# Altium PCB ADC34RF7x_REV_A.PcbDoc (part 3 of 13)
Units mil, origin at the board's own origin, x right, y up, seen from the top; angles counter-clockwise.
Board outline 6250 x 2716.54 mil, 18 copper layers (Top Layer, L2 GND, L3 PWR, L4 GND, L5 PWR/SIG, L6 GND, L7 SIGNAL, L8 GND, L9 GND, L10 SIGNAL, L11 GND, L12 SIGNAL, L13 GND, L14 PWR, L15 GND, L16 PWR/SIG, L16 GND, Bottom Layer), stack 95.314 mil thick; 668 components, 786 nets, 3150 pads, 2020 vias.
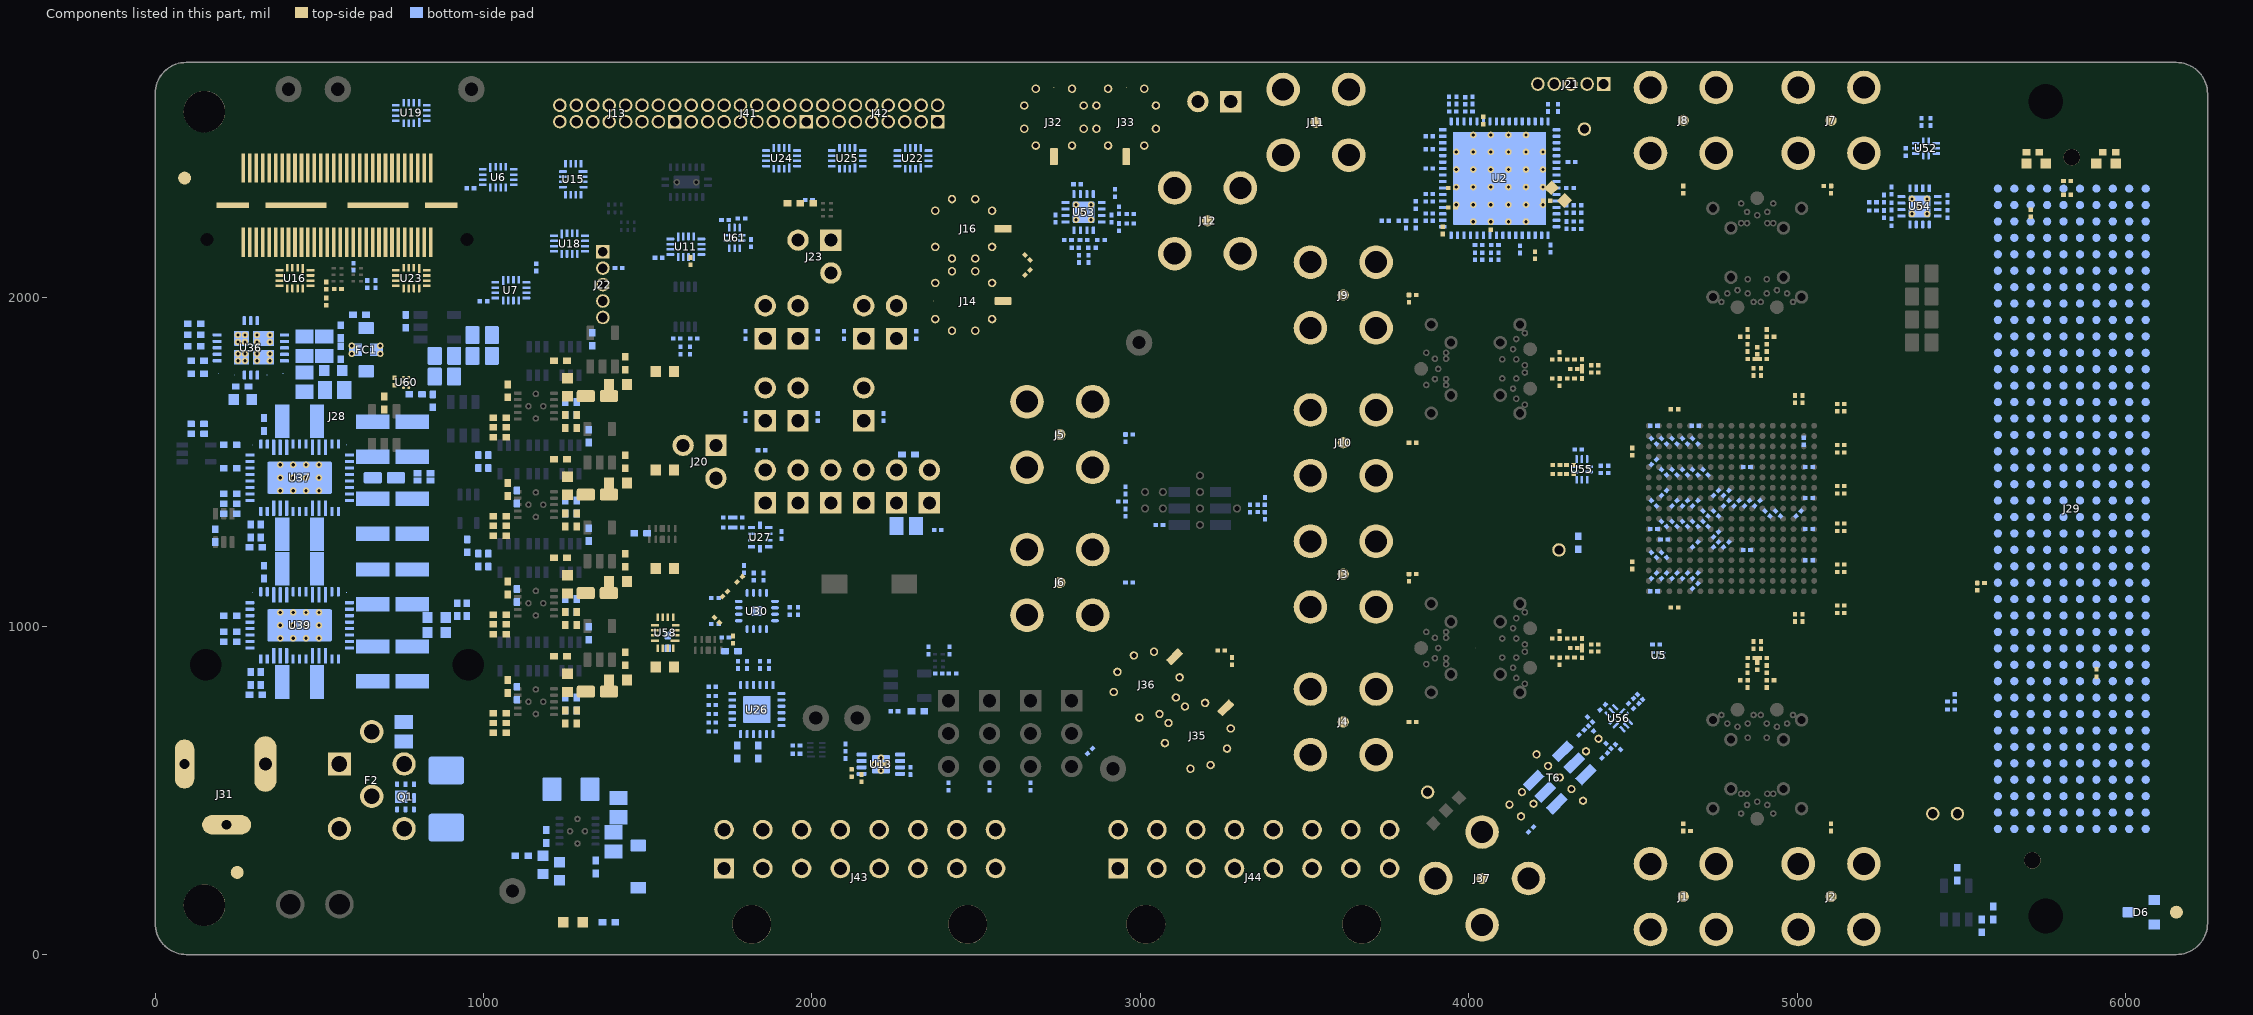
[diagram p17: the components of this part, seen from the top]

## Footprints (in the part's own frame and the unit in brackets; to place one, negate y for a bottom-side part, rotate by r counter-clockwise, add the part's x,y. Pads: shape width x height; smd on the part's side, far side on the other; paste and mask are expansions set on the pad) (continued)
NKD0064A [mm] "QFN, 64-Leads, Body 9x9mm, Pitch 0.5mm"
  rrect40% 0.6x0.25 smd mask+0.07: 1(-4.4,3.75) 2(-4.4,3.25) 3(-4.4,2.75) 4(-4.4,2.25) 5(-4.4,1.75) 6(-4.4,1.25) 7(-4.4,0.75) 8(-4.4,0.25) 9(-4.4,-0.25) 10(-4.4,-0.75) 11(-4.4,-1.25) 12(-4.4,-1.75) 13(-4.4,-2.25) 14(-4.4,-2.75) 15(-4.4,-3.25) 16(-4.4,-3.75) 33(4.4,-3.75) 34(4.4,-3.25) 35(4.4,-2.75) 36(4.4,-2.25) 37(4.4,-1.75) 38(4.4,-1.25) 39(4.4,-0.75) 40(4.4,-0.25) 41(4.4,0.25) 42(4.4,0.75) 43(4.4,1.25) 44(4.4,1.75) 45(4.4,2.25) 46(4.4,2.75) 47(4.4,3.25) 48(4.4,3.75)
  rrect40% 0.25x0.6 smd mask+0.07: 17(-3.75,-4.4) 18(-3.25,-4.4) 19(-2.75,-4.4) 20(-2.25,-4.4) 21(-1.75,-4.4) 22(-1.25,-4.4) 23(-0.75,-4.4) 24(-0.25,-4.4) 25(0.25,-4.4) 26(0.75,-4.4) 27(1.25,-4.4) 28(1.75,-4.4) 29(2.25,-4.4) 30(2.75,-4.4) 31(3.25,-4.4) 32(3.75,-4.4) 49(3.75,4.4) 50(3.25,4.4) 51(2.75,4.4) 52(2.25,4.4) 53(1.75,4.4) 54(1.25,4.4) 55(0.75,4.4) 56(0.25,4.4) 57(-0.25,4.4) 58(-0.75,4.4) 59(-1.25,4.4) 60(-1.75,4.4) 61(-2.25,4.4) 62(-2.75,4.4) 63(-3.25,4.4) 64(-3.75,4.4)
  round 0.508 hole 0.254 mask+0.102: 65(-3.35,-2.04) 65(-3.35,-0.68) 65(-3.35,0.68) 65(-3.35,2.04) 65(-2.04,-3.35) 65(-2.04,-2.04) 65(-2.04,-0.68) 65(-2.04,0.68) 65(-2.04,2.04) 65(-2.04,3.35) 65(-0.68,-3.35) 65(-0.68,-2.04) 65(-0.68,-0.68) 65(-0.68,0.68) 65(-0.68,2.04) 65(-0.68,3.35) 65(0.68,-3.35) 65(0.68,-2.04) 65(0.68,-0.68) 65(0.68,0.68) 65(0.68,2.04) 65(0.68,3.35) 65(2.04,-3.35) 65(2.04,-2.04) 65(2.04,-0.68) 65(2.04,0.68) 65(2.04,2.04) 65(2.04,3.35) 65(3.35,-2.04) 65(3.35,-0.68) 65(3.35,0.68) 65(3.35,2.04)
  rrect1% 7.2x7.2 smd paste-3.6 mask+0.07: 65(0,0)
  silkscreen extent -4.65,-4.65 4.65,4.65, body extent -4.55,-4.55 4.55,4.55, height 0.8
NKG0010A [mm]
  rrect50% 0.6x0.2 smd paste+0 mask+0.05: 1(-0.55,0.2) 2(-0.55,-0.2) 6(0.55,-0.2) 7(0.55,0.2)
  rrect50% 0.2x0.6 smd paste+0 mask+0.05: 3(-0.4,-0.8) 4(0,-0.8) 5(0.4,-0.8) 8(0.4,0.8) 9(0,0.8) 10(-0.4,0.8)
  silkscreen extent -1.07,0.47 -0.93,0.62, body extent -0.72,-0.93 0.72,0.93, height 0.56
PBC02SAAN [mm] "Sullins 100mil, 1x2, 230 mil above insulator"
  rect 1.65x1.65 hole 1.016: 1(0,1.27)
  round 1.65 hole 1.016: 2(0,-1.27)
  silkscreen extent -1.27,-2.54 1.6,2.54, body extent -1.27,-2.54 1.27,2.54, height 8.38
ProbePoint_TH_40mil [mil]
  round 41 hole 28: 1(0,0)
RAPC722X [mm] "Conn_DC Jack"
  oval 1.7x4.3 hole 1.01 slot 3.56 at 90 deg: 1(14.194,0)
  oval 1.5x3.8 hole 0.76 slot 3.05 at 90 deg: 2(7.946,0)
  oval 3.8x1.5 hole 0.76 slot 3.05 at 0 deg: 3(11.197,-4.7)
  silkscreen extent 0.2,-4.57 14.93,4.57, body extent 0.58,-4.97 15.06,4.56, height 10.92
RDB0051A [mm]
  round 0.025 smd mask+0.05: 1(-2.54,3.625) 15(-2.54,-3.625) 24(2.54,-3.625) 38(2.54,3.625)
  rrect30% 0.7x0.25 smd paste+0 mask+0.05: 2(-2.6,3) 3(-2.6,2.5) 7(-2.6,0.5) 8(-2.6,0) 9(-2.6,-0.5) 13(-2.6,-2.5) 14(-2.6,-3) 25(2.6,-3) 26(2.6,-2.5) 30(2.6,-0.5) 31(2.6,0) 32(2.6,0.5) 36(2.6,2.5) 37(2.6,3)
  rrect30% 1.2x0.25 smd paste+0 mask+0.05: 4(-2.35,2) 5(-2.35,1.5) 6(-2.35,1) 10(-2.35,-1) 11(-2.35,-1.5) 12(-2.35,-2) 27(2.35,-2) 28(2.35,-1.5) 29(2.35,-1) 33(2.35,1) 34(2.35,1.5) 35(2.35,2)
  rrect30% 0.25x0.7 smd paste+0 mask+0.05: 16(-1.75,-3.85) 17(-1.25,-3.85) 18(-0.75,-3.85) 19(-0.25,-3.85) 20(0.25,-3.85) 21(0.75,-3.85) 22(1.25,-3.85) 23(1.75,-3.85) 39(1.75,3.85) 40(1.25,3.85) 41(0.75,3.85) 42(0.25,3.85) 43(-0.25,3.85) 44(-0.75,3.85) 45(-1.25,3.85) 46(-1.75,3.85)
  rrect10% 2.5x5 smd paste-5: 47(0,0)
  round 0.508 hole 0.254 mask+0.102: 48(-1,1.5) 48(0,1.5) 48(1,1.5) 49(-1,0.5) 49(0,0.5) 49(1,0.5) 50(-1,-0.5) 50(0,-0.5) 50(1,-0.5) 51(-1,-1.5) 51(0,-1.5) 51(1,-1.5)
  Top Layer region: 2.955,-3.624 2.955,-3.425 2.951,-3.406 2.94,-3.389 2.924,-3.378 2.904,-3.375 2.904,-3.375 2.175,-3.375 2.156,-3.379 2.139,-3.39 2.129,-3.406 2.125,-3.426 2.125,-3.426 2.125,-3.825 2.129,-3.844 2.14,-3.861 2.157,-3.871 2.176,-3.875 2.176,-3.875 2.375,-3.875 2.394,-3.871 2.411,-3.86 2.422,-3.843 2.425,-3.824 2.425,-3.824 2.425,-3.726 2.429,-3.706 2.439,-3.69 2.456,-3.679 2.475,-3.675 2.475,-3.675 2.9,-3.675 2.921,-3.673 2.939,-3.662 2.951,-3.645 2.955,-3.624
  Top Layer region: -2.955,-3.624 -2.955,-3.425 -2.951,-3.406 -2.94,-3.389 -2.923,-3.378 -2.904,-3.375 -2.904,-3.375 -2.175,-3.375 -2.156,-3.379 -2.139,-3.39 -2.128,-3.406 -2.125,-3.426 -2.125,-3.426 -2.125,-3.825 -2.129,-3.844 -2.14,-3.861 -2.156,-3.871 -2.176,-3.875 -2.176,-3.875 -2.375,-3.875 -2.394,-3.871 -2.411,-3.86 -2.421,-3.843 -2.425,-3.824 -2.425,-3.824 -2.425,-3.726 -2.428,-3.706 -2.439,-3.69 -2.456,-3.679 -2.475,-3.675 -2.475,-3.675 -2.9,-3.675 -2.921,-3.673 -2.939,-3.662 -2.951,-3.645 -2.955,-3.624
  Top Layer region: 2.955,3.624 2.955,3.425 2.951,3.406 2.94,3.389 2.924,3.379 2.904,3.375 2.904,3.375 2.175,3.375 2.156,3.379 2.139,3.39 2.129,3.407 2.125,3.426 2.125,3.426 2.125,3.825 2.129,3.844 2.14,3.861 2.157,3.872 2.176,3.875 2.176,3.875 2.375,3.875 2.394,3.871 2.411,3.86 2.422,3.844 2.425,3.824 2.425,3.824 2.425,3.726 2.429,3.707 2.439,3.69 2.456,3.679 2.475,3.675 2.475,3.675 2.9,3.675 2.921,3.673 2.939,3.662 2.951,3.645 2.955,3.624
  Top Layer region: -2.955,3.624 -2.955,3.425 -2.951,3.406 -2.94,3.389 -2.923,3.379 -2.904,3.375 -2.904,3.375 -2.175,3.375 -2.156,3.379 -2.139,3.39 -2.128,3.407 -2.125,3.426 -2.125,3.426 -2.125,3.825 -2.129,3.844 -2.14,3.861 -2.156,3.872 -2.176,3.875 -2.176,3.875 -2.375,3.875 -2.394,3.871 -2.411,3.86 -2.421,3.844 -2.425,3.824 -2.425,3.824 -2.425,3.726 -2.428,3.707 -2.439,3.69 -2.456,3.679 -2.475,3.675 -2.475,3.675 -2.9,3.675 -2.921,3.673 -2.939,3.662 -2.951,3.645 -2.955,3.624
  silkscreen extent -3.65,-4.3 2.8,4.3, body extent -2.75,-4 2.75,4, height 1.8
RDU0028A [mm]
  round 0.025 smd mask+0.05: 1(-1.987,2.487) 2(-2.1,1.25) 6(-2.1,-1.25) 7(-1.987,-2.488) 13(1.987,-2.488) 14(2.1,-1.25) 18(2.1,1.25) 19(1.988,2.488)
  rrect40% 0.7x0.25 smd paste+0 mask+0.05: 3(-2.1,0.5) 4(-2.1,0) 5(-2.1,-0.5) 15(2.1,-0.5) 16(2.1,0) 17(2.1,0.5)
  rrect40% 0.25x0.7 smd paste+0 mask+0.05: 8(-1,-2.6) 9(-0.5,-2.6) 10(0,-2.6) 11(0.5,-2.6) 12(1,-2.6) 20(1,2.6) 21(0.5,2.6) 22(0,2.6) 23(-0.5,2.6) 24(-1,2.6)
  round 0.508 hole 0.254 mask+0.102: 25(-1,1) 25(-1,0.45) 25(-0.45,1) 25(-0.45,0.45) 26(-1,-1.475) 26(-1,-0.475) 26(-0.45,-1.475) 26(-0.45,-0.475) 27(0.45,-1.475) 27(0.45,-0.475) 27(1,-1.475) 27(1,-0.475) 28(0.45,1) 28(0.45,0.45) 28(1,1) 28(1,0.45)
  rrect9% 1.15x1.15 smd paste-1000 mask+0.05: 25(-0.725,0.725) 28(0.725,0.725)
  rrect9% 1.15x1.65 smd paste-1000 mask+0.05: 26(-0.725,-0.975) 27(0.725,-0.975)
  Top Layer region: -2.4,1.625 -1.8,1.625 -1.781,1.621 -1.765,1.61 -1.754,1.594 -1.75,1.575 -1.75,1.575 -1.75,0.925 -1.754,0.906 -1.765,0.89 -1.781,0.879 -1.8,0.875 -1.8,0.875 -2.4,0.875 -2.419,0.879 -2.435,0.89 -2.446,0.906 -2.45,0.925 -2.45,0.925 -2.45,1.075 -2.443,1.1 -2.425,1.118 -2.4,1.125 -2.4,1.125 -2.225,1.125 -2.187,1.133 -2.154,1.154 -2.133,1.187 -2.125,1.225 -2.125,1.225 -2.125,1.275 -2.138,1.325 -2.175,1.362 -2.225,1.375 -2.225,1.375 -2.4,1.375 -2.419,1.379 -2.435,1.39 -2.446,1.406 -2.45,1.425 -2.45,1.425 -2.45,1.575 -2.443,1.6 -2.425,1.618 -2.4,1.625
  Top Layer region: -1.575,-2.95 -1.55,-2.943 -1.532,-2.925 -1.525,-2.9 -1.525,-2.9 -1.525,-2.075 -1.529,-2.056 -1.54,-2.04 -1.556,-2.029 -1.575,-2.025 -1.575,-2.025 -2.4,-2.025 -2.423,-2.033 -2.439,-2.051 -2.445,-2.075 -2.445,-2.075 -2.45,-2.225 -2.443,-2.25 -2.425,-2.268 -2.4,-2.275 -2.4,-2.275 -2.225,-2.275 -2.187,-2.283 -2.154,-2.304 -2.133,-2.337 -2.125,-2.375 -2.125,-2.375 -2.125,-2.575 -2.118,-2.6 -2.1,-2.618 -2.075,-2.625 -2.075,-2.625 -1.875,-2.625 -1.837,-2.633 -1.804,-2.654 -1.783,-2.687 -1.775,-2.725 -1.775,-2.725 -1.775,-2.9 -1.768,-2.925 -1.75,-2.943 -1.725,-2.95 -1.725,-2.95
  Top Layer region: -1.575,2.95 -1.55,2.943 -1.532,2.925 -1.525,2.9 -1.525,2.9 -1.525,2.075 -1.529,2.056 -1.54,2.04 -1.556,2.029 -1.575,2.025 -1.575,2.025 -2.4,2.025 -2.423,2.033 -2.439,2.051 -2.445,2.075 -2.445,2.075 -2.45,2.225 -2.443,2.25 -2.425,2.268 -2.4,2.275 -2.4,2.275 -2.225,2.275 -2.187,2.283 -2.154,2.304 -2.133,2.337 -2.125,2.375 -2.125,2.375 -2.125,2.575 -2.118,2.6 -2.1,2.618 -2.075,2.625 -2.075,2.625 -1.875,2.625 -1.837,2.633 -1.804,2.654 -1.783,2.687 -1.775,2.725 -1.775,2.725 -1.775,2.9 -1.768,2.925 -1.75,2.943 -1.725,2.95 -1.725,2.95
  Top Layer region: -2.4,-0.875 -1.8,-0.875 -1.775,-0.882 -1.757,-0.9 -1.75,-0.925 -1.75,-0.925 -1.75,-1.575 -1.754,-1.594 -1.765,-1.61 -1.781,-1.621 -1.8,-1.625 -1.8,-1.625 -2.4,-1.625 -2.419,-1.621 -2.435,-1.61 -2.446,-1.594 -2.45,-1.575 -2.45,-1.575 -2.45,-1.425 -2.443,-1.4 -2.425,-1.382 -2.4,-1.375 -2.4,-1.375 -2.225,-1.375 -2.187,-1.367 -2.154,-1.346 -2.133,-1.313 -2.125,-1.275 -2.125,-1.275 -2.125,-1.225 -2.138,-1.175 -2.175,-1.138 -2.225,-1.125 -2.225,-1.125 -2.4,-1.125 -2.419,-1.121 -2.435,-1.11 -2.446,-1.094 -2.45,-1.075 -2.45,-1.075 -2.45,-0.925 -2.443,-0.9 -2.425,-0.882 -2.4,-0.875
  Top Layer region: 2.4,0.875 1.8,0.875 1.775,0.882 1.757,0.9 1.75,0.925 1.75,0.925 1.75,1.575 1.754,1.594 1.765,1.61 1.781,1.621 1.8,1.625 1.8,1.625 2.4,1.625 2.419,1.621 2.435,1.61 2.446,1.594 2.45,1.575 2.45,1.575 2.45,1.425 2.443,1.4 2.425,1.382 2.4,1.375 2.4,1.375 2.225,1.375 2.187,1.367 2.154,1.346 2.133,1.313 2.125,1.275 2.125,1.275 2.125,1.225 2.138,1.175 2.175,1.138 2.225,1.125 2.225,1.125 2.4,1.125 2.419,1.121 2.435,1.11 2.446,1.094 2.45,1.075 2.45,1.075 2.45,0.925 2.443,0.9 2.425,0.882 2.4,0.875
  Top Layer region: 1.575,-2.95 1.55,-2.943 1.532,-2.925 1.525,-2.9 1.525,-2.9 1.525,-2.075 1.529,-2.056 1.54,-2.04 1.556,-2.029 1.575,-2.025 1.575,-2.025 2.4,-2.025 2.423,-2.033 2.439,-2.051 2.445,-2.075 2.445,-2.075 2.45,-2.225 2.443,-2.25 2.425,-2.268 2.4,-2.275 2.4,-2.275 2.225,-2.275 2.187,-2.283 2.154,-2.304 2.133,-2.337 2.125,-2.375 2.125,-2.375 2.125,-2.575 2.118,-2.6 2.1,-2.618 2.075,-2.625 2.075,-2.625 1.875,-2.625 1.837,-2.633 1.804,-2.654 1.783,-2.687 1.775,-2.725 1.775,-2.725 1.775,-2.9 1.768,-2.925 1.75,-2.943 1.725,-2.95 1.725,-2.95
  Top Layer region: 2.4,-1.625 1.8,-1.625 1.775,-1.618 1.757,-1.6 1.75,-1.575 1.75,-1.575 1.75,-0.925 1.754,-0.906 1.765,-0.89 1.781,-0.879 1.8,-0.875 1.8,-0.875 2.4,-0.875 2.419,-0.879 2.435,-0.89 2.446,-0.906 2.45,-0.925 2.45,-0.925 2.45,-1.075 2.443,-1.1 2.425,-1.118 2.4,-1.125 2.4,-1.125 2.225,-1.125 2.187,-1.133 2.154,-1.154 2.133,-1.187 2.125,-1.225 2.125,-1.225 2.125,-1.275 2.138,-1.325 2.175,-1.362 2.225,-1.375 2.225,-1.375 2.4,-1.375 2.419,-1.379 2.435,-1.39 2.446,-1.406 2.45,-1.425 2.45,-1.425 2.45,-1.575 2.443,-1.6 2.425,-1.618 2.4,-1.625
  Top Layer region: 1.575,2.95 1.55,2.943 1.532,2.925 1.525,2.9 1.525,2.9 1.525,2.075 1.529,2.056 1.54,2.04 1.556,2.029 1.575,2.025 1.575,2.025 2.4,2.025 2.423,2.033 2.439,2.051 2.445,2.075 2.445,2.075 2.45,2.225 2.443,2.25 2.425,2.268 2.4,2.275 2.4,2.275 2.225,2.275 2.187,2.283 2.154,2.304 2.133,2.337 2.125,2.375 2.125,2.375 2.125,2.575 2.118,2.6 2.1,2.618 2.075,2.625 2.075,2.625 1.875,2.625 1.837,2.633 1.804,2.654 1.783,2.687 1.775,2.725 1.775,2.725 1.775,2.9 1.768,2.925 1.75,2.943 1.725,2.95 1.725,2.95
  silkscreen extent -3.2,-3.13 2.63,3.13, body extent -2.25,-2.75 2.25,2.75, height 1.9
RGE0024C [mm] "VQFN-24"
  rrect42% 0.6x0.24 smd: 1(-1.9,1.25) 2(-1.9,0.75) 3(-1.9,0.25) 4(-1.9,-0.25) 5(-1.9,-0.75) 6(-1.9,-1.25) 13(1.9,-1.25) 14(1.9,-0.75) 15(1.9,-0.25) 16(1.9,0.25) 17(1.9,0.75) 18(1.9,1.25)
  rrect42% 0.24x0.6 smd: 7(-1.25,-1.9) 8(-0.75,-1.9) 9(-0.25,-1.9) 10(0.25,-1.9) 11(0.75,-1.9) 12(1.25,-1.9) 19(1.25,1.9) 20(0.75,1.9) 21(0.25,1.9) 22(-0.25,1.9) 23(-0.75,1.9) 24(-1.25,1.9)
  rrect5% 2.1x2.1 smd paste-1.05: 25(0,0)
  body extent -2,-2 2,2, height 1
RGT0016C [mm]
  rrect30% 0.6x0.24 smd paste+0 mask+0.07: 1(-1.4,0.75) 2(-1.4,0.25) 3(-1.4,-0.25) 4(-1.4,-0.75) 9(1.4,-0.75) 10(1.4,-0.25) 11(1.4,0.25) 12(1.4,0.75)
  rrect30% 0.24x0.6 smd paste+0 mask+0.07: 5(-0.75,-1.4) 6(-0.25,-1.4) 7(0.25,-1.4) 8(0.75,-1.4) 13(0.75,1.4) 14(0.25,1.4) 15(-0.25,1.4) 16(-0.75,1.4)
  round 0.508 hole 0.254 mask+0.05: 17(-0.58,-0.58) 17(-0.58,0.58) 17(0,0) 17(0.58,-0.58) 17(0.58,0.58)
  rrect10% 1.68x1.68 smd paste-0.065 mask+0.07: 17(0,0)
  silkscreen extent -1.97,-1.68 1.68,1.68, body extent -1.5,-1.5 1.5,1.5, height 1
RSV0016A [mm] "QFN, 16-Leads, Body 1.8x2.6mm, Pitch 0.4mm, TI Recommended"
  rrect25% 0.7x0.2 smd mask+0.05: 1(-0.75,0.6)
  rrect25% 0.6x0.2 smd mask+0.05: 2(-0.8,0.2) 3(-0.8,-0.2) 4(-0.8,-0.6) 9(0.8,-0.6) 10(0.8,-0.2) 11(0.8,0.2) 12(0.8,0.6)
  rrect25% 0.2x0.6 smd mask+0.05: 5(-0.6,-1.2) 6(-0.2,-1.2) 7(0.2,-1.2) 8(0.6,-1.2) 13(0.6,1.2) 14(0.2,1.2) 15(-0.2,1.2) 16(-0.6,1.2)
  silkscreen extent -1.08,-1.33 1.08,1.45, body extent -0.85,-1.31 0.85,1.31, height 0.49
RTE0016D [mm] "QFN, 16-Leads, Body 3x3mm, Pitch 0.5mm"
  oval 0.6x0.24 smd: 1(-1.4,0.75) 2(-1.4,0.25) 3(-1.4,-0.25) 4(-1.4,-0.75) 9(1.4,-0.75) 10(1.4,-0.25) 11(1.4,0.25) 12(1.4,0.75)
  oval 0.24x0.6 smd: 5(-0.75,-1.4) 6(-0.25,-1.4) 7(0.25,-1.4) 8(0.75,-1.4) 13(0.75,1.4) 14(0.25,1.4) 15(-0.25,1.4) 16(-0.75,1.4)
  rect 0.8x0.8 smd paste-0.85: 17(0,0)
  silkscreen extent -1.72,-1.73 1.72,1.73, body extent -1.57,-1.57 1.58,1.58, height 0.81
RUG0010A [mm] "QFN, 10-Leads, Body 2x1.5mm. Pitch 0.5mm, TI Recommended"
  rect 0.55x0.25 smd: 1(-0.675,0.75) 4(-0.675,-0.75) 6(0.675,-0.75) 9(0.675,0.75)
  rect 0.55x0.2 smd: 2(-0.675,0.25) 3(-0.675,-0.25) 7(0.675,-0.25) 8(0.675,0.25)
  rect 0.3x0.575 smd: 5(0,-0.913) 10(0,0.913)
  silkscreen extent -0.9,-1.15 0.9,1.15, body extent -0.77,-1.02 0.77,1.02, height 0.41
SAMTEC_ASP-134488-01 [mm]
  round 0.64 smd paste+0.125: A1(24.74,5.715) A2(23.47,5.715) A3(22.2,5.715) A4(20.93,5.715) A5(19.66,5.715) A6(18.39,5.715) A7(17.12,5.715) A8(15.85,5.715) A9(14.58,5.715) A10(13.31,5.715) A11(12.04,5.715) A12(10.77,5.715) A13(9.5,5.715) A14(8.23,5.715) A15(6.96,5.715) A16(5.69,5.715) A17(4.42,5.715) A18(3.15,5.715) A19(1.88,5.715) A20(0.61,5.715) A21(-0.66,5.715) A22(-1.93,5.715) A23(-3.2,5.715) A24(-4.47,5.715) A25(-5.74,5.715) A26(-7.01,5.715) A27(-8.28,5.715) A28(-9.55,5.715) A29(-10.82,5.715) A30(-12.09,5.715) A31(-13.36,5.715) A32(-14.63,5.715) A33(-15.9,5.715) A34(-17.17,5.715) A35(-18.44,5.715) A36(-19.71,5.715) A37(-20.98,5.715) A38(-22.25,5.715) A39(-23.52,5.715) A40(-24.79,5.715) B1(24.74,4.445) B2(23.47,4.445) B3(22.2,4.445) B4(20.93,4.445) B5(19.66,4.445) B6(18.39,4.445) B7(17.12,4.445) B8(15.85,4.445) B9(14.58,4.445) B10(13.31,4.445) B11(12.04,4.445) B12(10.77,4.445) B13(9.5,4.445) B14(8.23,4.445) B15(6.96,4.445) B16(5.69,4.445) B17(4.42,4.445) B18(3.15,4.445) B19(1.88,4.445) B20(0.61,4.445) B21(-0.66,4.445) B22(-1.93,4.445) B23(-3.2,4.445) B24(-4.47,4.445) B25(-5.74,4.445) B26(-7.01,4.445) B27(-8.28,4.445) B28(-9.55,4.445) B29(-10.82,4.445) B30(-12.09,4.445) B31(-13.36,4.445) B32(-14.63,4.445) B33(-15.9,4.445) B34(-17.17,4.445) B35(-18.44,4.445) B36(-19.71,4.445) B37(-20.98,4.445) B38(-22.25,4.445) B39(-23.52,4.445) B40(-24.79,4.445) C1(24.74,3.175) C2(23.47,3.175) C3(22.2,3.175) C4(20.93,3.175) C5(19.66,3.175) C6(18.39,3.175) C7(17.12,3.175) C8(15.85,3.175) C9(14.58,3.175) C10(13.31,3.175) C11(12.04,3.175) C12(10.77,3.175) C13(9.5,3.175) C14(8.23,3.175) C15(6.96,3.175) C16(5.69,3.175) C17(4.42,3.175) C18(3.15,3.175) C19(1.88,3.175) C20(0.61,3.175) C21(-0.66,3.175) C22(-1.93,3.175) C23(-3.2,3.175) C24(-4.47,3.175) C25(-5.74,3.175) C26(-7.01,3.175) C27(-8.28,3.175) C28(-9.55,3.175) C29(-10.82,3.175) C30(-12.09,3.175) C31(-13.36,3.175) C32(-14.63,3.175) C33(-15.9,3.175) C34(-17.17,3.175) C35(-18.44,3.175) C36(-19.71,3.175) C37(-20.98,3.175) C38(-22.25,3.175) C39(-23.52,3.175) C40(-24.79,3.175) D1(24.74,1.905) D2(23.47,1.905) D3(22.2,1.905) D4(20.93,1.905) D5(19.66,1.905) D6(18.39,1.905) D7(17.12,1.905) D8(15.85,1.905) D9(14.58,1.905) D10(13.31,1.905) D11(12.04,1.905) D12(10.77,1.905) D13(9.5,1.905) D14(8.23,1.905) D15(6.96,1.905) D16(5.69,1.905) D17(4.42,1.905) D18(3.15,1.905) D19(1.88,1.905) D20(0.61,1.905) D21(-0.66,1.905) D22(-1.93,1.905) D23(-3.2,1.905) D24(-4.47,1.905) D25(-5.74,1.905) D26(-7.01,1.905) D27(-8.28,1.905) D28(-9.55,1.905) D29(-10.82,1.905) D30(-12.09,1.905) D31(-13.36,1.905) D32(-14.63,1.905) D33(-15.9,1.905) D34(-17.17,1.905) D35(-18.44,1.905) D36(-19.71,1.905) D37(-20.98,1.905) D38(-22.25,1.905) D39(-23.52,1.905) D40(-24.79,1.905) E1(24.74,0.635) E2(23.47,0.635) E3(22.2,0.635) E4(20.93,0.635) E5(19.66,0.635) E6(18.39,0.635) E7(17.12,0.635) E8(15.85,0.635) E9(14.58,0.635) E10(13.31,0.635) E11(12.04,0.635) E12(10.77,0.635) E13(9.5,0.635) E14(8.23,0.635) E15(6.96,0.635) E16(5.69,0.635) E17(4.42,0.635) E18(3.15,0.635) E19(1.88,0.635) E20(0.61,0.635) E21(-0.66,0.635) E22(-1.93,0.635) E23(-3.2,0.635) E24(-4.47,0.635) E25(-5.74,0.635) E26(-7.01,0.635) E27(-8.28,0.635) E28(-9.55,0.635) E29(-10.82,0.635) E30(-12.09,0.635) E31(-13.36,0.635) E32(-14.63,0.635) E33(-15.9,0.635) E34(-17.17,0.635) E35(-18.44,0.635) E36(-19.71,0.635) E37(-20.98,0.635) E38(-22.25,0.635) E39(-23.52,0.635) E40(-24.79,0.635) F1(24.74,-0.635) F2(23.47,-0.635) F3(22.2,-0.635) F4(20.93,-0.635) F5(19.66,-0.635) F6(18.39,-0.635) F7(17.12,-0.635) F8(15.85,-0.635) F9(14.58,-0.635) F10(13.31,-0.635) F11(12.04,-0.635) F12(10.77,-0.635) F13(9.5,-0.635) F14(8.23,-0.635) F15(6.96,-0.635) F16(5.69,-0.635) F17(4.42,-0.635) F18(3.15,-0.635) F19(1.88,-0.635) F20(0.61,-0.635) F21(-0.66,-0.635) F22(-1.93,-0.635) F23(-3.2,-0.635) F24(-4.47,-0.635) F25(-5.74,-0.635) F26(-7.01,-0.635) F27(-8.28,-0.635) F28(-9.55,-0.635) F29(-10.82,-0.635) F30(-12.09,-0.635) F31(-13.36,-0.635) F32(-14.63,-0.635) F33(-15.9,-0.635) F34(-17.17,-0.635) F35(-18.44,-0.635) F36(-19.71,-0.635) F37(-20.98,-0.635) F38(-22.25,-0.635) F39(-23.52,-0.635) F40(-24.79,-0.635) G1(24.74,-1.905) G2(23.47,-1.905) G3(22.2,-1.905) G4(20.93,-1.905) G5(19.66,-1.905) G6(18.39,-1.905) G7(17.12,-1.905) G8(15.85,-1.905) G9(14.58,-1.905) G10(13.31,-1.905) G11(12.04,-1.905) G12(10.77,-1.905) G13(9.5,-1.905) G14(8.23,-1.905) G15(6.96,-1.905) G16(5.69,-1.905) G17(4.42,-1.905) G18(3.15,-1.905) G19(1.88,-1.905) G20(0.61,-1.905) G21(-0.66,-1.905) G22(-1.93,-1.905) G23(-3.2,-1.905) G24(-4.47,-1.905) G25(-5.74,-1.905) G26(-7.01,-1.905) G27(-8.28,-1.905) G28(-9.55,-1.905) G29(-10.82,-1.905) G30(-12.09,-1.905) G31(-13.36,-1.905) G32(-14.63,-1.905) G33(-15.9,-1.905) G34(-17.17,-1.905) G35(-18.44,-1.905) G36(-19.71,-1.905) G37(-20.98,-1.905) G38(-22.25,-1.905) G39(-23.52,-1.905) G40(-24.79,-1.905) H1(24.74,-3.175) H2(23.47,-3.175) H3(22.2,-3.175) H4(20.93,-3.175) H5(19.66,-3.175) H6(18.39,-3.175) H7(17.12,-3.175) H8(15.85,-3.175) H9(14.58,-3.175) H10(13.31,-3.175) H11(12.04,-3.175) H12(10.77,-3.175) H13(9.5,-3.175) H14(8.23,-3.175) H15(6.96,-3.175) H16(5.69,-3.175) H17(4.42,-3.175) H18(3.15,-3.175) H19(1.88,-3.175) H20(0.61,-3.175) H21(-0.66,-3.175) H22(-1.93,-3.175) H23(-3.2,-3.175) H24(-4.47,-3.175) H25(-5.74,-3.175) H26(-7.01,-3.175) H27(-8.28,-3.175) H28(-9.55,-3.175) H29(-10.82,-3.175) H30(-12.09,-3.175) H31(-13.36,-3.175) H32(-14.63,-3.175) H33(-15.9,-3.175) H34(-17.17,-3.175) H35(-18.44,-3.175) H36(-19.71,-3.175) H37(-20.98,-3.175) H38(-22.25,-3.175) H39(-23.52,-3.175) H40(-24.79,-3.175) J1(24.74,-4.445) J2(23.47,-4.445) J3(22.2,-4.445) J4(20.93,-4.445) J5(19.66,-4.445) J6(18.39,-4.445) J7(17.12,-4.445) J8(15.85,-4.445) J9(14.58,-4.445) J10(13.31,-4.445) J11(12.04,-4.445) J12(10.77,-4.445) J13(9.5,-4.445) J14(8.23,-4.445) J15(6.96,-4.445) J16(5.69,-4.445) J17(4.42,-4.445) J18(3.15,-4.445) J19(1.88,-4.445) J20(0.61,-4.445) J21(-0.66,-4.445) J22(-1.93,-4.445) J23(-3.2,-4.445) J24(-4.47,-4.445) J25(-5.74,-4.445) J26(-7.01,-4.445) J27(-8.28,-4.445) J28(-9.55,-4.445) J29(-10.82,-4.445) J30(-12.09,-4.445) J31(-13.36,-4.445) J32(-14.63,-4.445) J33(-15.9,-4.445) J34(-17.17,-4.445) J35(-18.44,-4.445) J36(-19.71,-4.445) J37(-20.98,-4.445) J38(-22.25,-4.445) J39(-23.52,-4.445) J40(-24.79,-4.445) K1(24.74,-5.715) K2(23.47,-5.715) K3(22.2,-5.715) K4(20.93,-5.715) K5(19.66,-5.715) K6(18.39,-5.715) K7(17.12,-5.715) K8(15.85,-5.715) K9(14.58,-5.715) K10(13.31,-5.715) K11(12.04,-5.715) K12(10.77,-5.715) K13(9.5,-5.715) K14(8.23,-5.715) K15(6.96,-5.715) K16(5.69,-5.715) K17(4.42,-5.715) K18(3.15,-5.715) K19(1.88,-5.715) K20(0.61,-5.715) K21(-0.66,-5.715) K22(-1.93,-5.715) K23(-3.2,-5.715) K24(-4.47,-5.715) K25(-5.74,-5.715) K26(-7.01,-5.715) K27(-8.28,-5.715) K28(-9.55,-5.715) K29(-10.82,-5.715) K30(-12.09,-5.715) K31(-13.36,-5.715) K32(-14.63,-5.715) K33(-15.9,-5.715) K34(-17.17,-5.715) K35(-18.44,-5.715) K36(-19.71,-5.715) K37(-20.98,-5.715) K38(-22.25,-5.715) K39(-23.52,-5.715) K40(-24.79,-5.715)
  round 0 hole 2.69 unplated: ""(-31.521,-2.007) ""(31.471,-2.007)
  round 1.27 hole 1.27 unplated: ""(-27.216,-3.05) ""(27.166,0)
  silkscreen extent -27.92,-7.34 28.75,7.76, body extent -27.91,-7.34 28.76,7.34, height 7.11
SF-1206F500M-2_1206 [mm]
  rrect7% 1.45x1.8 smd paste+0 mask+0.05: 1(-1.475,0) 2(1.475,0)
  silkscreen extent -0.55,-0.9 0.55,0.9, body extent -1.6,-0.8 1.6,0.8, height 1.05
SMBJ15CA [mil]
  rrect20% 85x107.99 smd: 1(-87.01,0) 2(87.01,0)
  silkscreen extent -125,-79 125,79, body extent -104,-73 104,73, height 89
SOD-123 [mm] "On Semi recommended land pattern"
  rrect20% 0.915x1.22 smd: 1(-1.637,0) 2(1.637,0)
  silkscreen extent -2.74,-1.17 2.03,1.17, body extent -1.93,-0.9 1.93,0.9, height 1.35
SOT-323-DIO [mm]
  rrect21% 0.9x0.8 smd: 1(-1,0.95) 2(-1,-0.95) 3(1,0)
  silkscreen extent -1.14,-1.52 0.77,1.52, body extent -1.25,-1.5 1.24,1.5, height 1.2
SPC02SYAN [mil] "SULLINS"
  round 1 on Mech3: 0(0,0)
  body extent -98,-47 99,47, height 366
TCM2-43X+ [mm]
  rrect10% 0.76x1.65 smd: 1(-1.27,1.59) 2(0,1.59) 3(1.27,1.59) 4(1.27,-1.59) 5(0,-1.59) 6(-1.27,-1.59)
  round 0.635 hole 0.381 mask+0.05: 5(-2.54,0) 5(-1.27,4.242) 5(-1.27,0) 5(-1.27,2.87) 5(0,0) 5(0,-4.242) 5(0,-2.87) 5(0,2.87) 5(0,4.242) 5(1.27,0) 5(2.54,0)
  silkscreen extent -1.91,-1.91 1.91,3.09, body extent -1.91,-1.91 1.9,1.9, height 3.13
TDFN8 [mm]
  rrect30% 0.75x0.3 smd paste+0 mask+0.05: 1(-1.5,0.75) 2(-1.5,0.25) 3(-1.5,-0.25) 4(-1.5,-0.75) 5(1.478,-0.75) 6(1.478,-0.25) 7(1.478,0.25) 8(1.478,0.75)
  round 0.508 hole 0.254 mask+0.05: 9(-0.5,0) 9(0,-0.5) 9(0,0) 9(0,0.5) 9(0.5,0)
  rrect10% 1.36x1.46 smd paste+0 mask+0.05: 9(0,0)
  silkscreen extent -2.23,0.67 -2.14,0.83, body extent -1.5,-1 1.5,1, height 0.75
TI_Stacked_Overlay_Medium [mil]
  silkscreen extent -576,-136 575,134
WEEE_Minimum [mil] "WEEElie bin"
  silkscreen extent -95,-172 99,104
YBG0006AJAP [mm] "DSBGA-6"
  round 0.23 smd paste-0.23 mask+0.032: A1(-0.2,0.4) A2(0.2,0.4) B1(-0.2,0) B2(0.2,0) C1(-0.2,-0.4) C2(0.2,-0.4)
  body extent -0.34,-0.54 0.34,0.54, height 0.33

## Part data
C1 C2 C3 C4 C6 C7 C8 C9 C10 C11 C12 C14 C15 C16 C17 C18 C19 C20 C21 C22 C23 C24 C25 C26 C27 C28 C30 C31 C32 C33 C34 C35 C36 C38 C39 C40 C55 C56 C66 C67 C75 C76 C77 C78 C79 C80 C81 C82 C83 C84 C85 C86 C87 C88 C89 C90 C91 C99 C265: library part 0201RFCaps0693, "Broadband Capacitors", Alt Manufacturer="Murata Electronics", Alt PartNumber=GRM033C71C104ME14D, Manufacturer="Passive Plus", Operating Temperature="-55°C ~ 125°C", Temperature Coefficient="C0G, NP0", Tolerance=±10%, Voltage - Rated=16V
C5 C13 C29 C37: library part capcc09263, "CAP CER 0.1UF 16V X7R 0201", Manufacturer="Murata Electronics", Operating Temperature="-55°C ~ 125°C", Ratings=-, Supplier Part Number 1=490-GRM033Z71C104KE14DCT-ND, Temperature Coefficient=X7R, Tolerance=±10%, Voltage - Rated=16V
C41 C42 C43 C44 C45 C46 C47 C48 C49 C50 C51 C52 C53 C54 C57 C59 C61 C62 C63 C64 C65 C68 C70 C73 C93 C100 C101 C105 C110 C111 C112 C115 C116 C117 C121 C123 C125 C127 C129 C132 C133 C134 C135 C136 C137 C138 C141 C142 C143 C148 C149 C150 C151 C152 C153 C154 C155 C156 C158 C159 C160 C161 C162 C163 C166 C168 C169 C178 C179 C180 C181 C182 C183 C185 C186 C256 C258 C259 C260 C261 C262 C263 C264: library part capcc01294, "CAP CER 0.1UF 25V X5R 0201", Manufacturer="TDK Corporation", Operating Temperature="-55°C ~ 85°C", Ratings=-, Supplier Part Number 1=445-13671-1-ND, Temperature Coefficient=X5R, Tolerance=±10%, Voltage - Rated=25V
C58: library part capcc03260, "CAP CER 2.2UF 25V X5R 0402", Manufacturer="TDK Corporation", Operating Temperature="-55°C ~ 85°C", Ratings=-, Supplier Part Number 1=445-9090-1-ND, Temperature Coefficient=X5R, Tolerance=±10%, Voltage - Rated=25V
C60 C92: library part capcc09406, "CAP CER 10UF 10V X5R 0402", Manufacturer="KYOCERA AVX", Operating Temperature="-55°C ~ 85°C", Ratings=-, Supplier Part Number 1=478-10052-1-ND, Temperature Coefficient=X5R, Tolerance=±20%, Voltage - Rated=10V
C69 C228: library part capcc01268, "CAP CER 0.1UF 50V X5R 0402", Manufacturer="TDK Corporation", Operating Temperature="-55°C ~ 85°C", Ratings=-, Supplier Part Number 1=445-5942-1-ND, Temperature Coefficient=X5R, Tolerance=±10%, Voltage - Rated=50V
C71 C95 C96: library part capcc02687, "CAP CER 1UF 50V X7R 0805", Manufacturer="TDK Corporation", Operating Temperature="-55°C ~ 125°C", Ratings=-, Supplier Part Number 1=445-7547-1-ND, Temperature Coefficient=X7R, Tolerance=±10%, Voltage - Rated=50V
C72 C126 C229 C236 C243 C250: library part capcc03657, "CAP CER 10UF 10V X5R 0603", Manufacturer="KYOCERA AVX", Operating Temperature="-55°C ~ 85°C", Ratings=-, Supplier Part Number 1=478-10766-1-ND, Temperature Coefficient=X5R, Tolerance=±10%, Voltage - Rated=10V
C74 C218 C227: library part capcc03154, "CAP CER 2.2UF 16V X6S 0402", Manufacturer="TDK Corporation", Operating Temperature="-55°C ~ 105°C", Ratings=-, Supplier Part Number 1=445-9103-1-ND, Temperature Coefficient=X6S, Tolerance=±10%, Voltage - Rated=16V
C94 C102 C103 C104 C106 C107 C175 C176 C177 C235 C242 C249: library part capcc01277, "CAP CER 0.1UF 6.3V X5R 0402", Manufacturer="KYOCERA AVX", Operating Temperature="-55°C ~ 85°C", Ratings=-, Supplier Part Number 1=478-11504-1-ND, Temperature Coefficient=X5R, Tolerance=±10%, Voltage - Rated=6.3V
C97 C98: library part capcc03751, "CAP CER 1000PF 50V X7R 0603", Manufacturer="TDK Corporation", Operating Temperature="-55°C ~ 125°C", Ratings=AEC-Q200, Supplier Part Number 1=445-5659-1-ND, Temperature Coefficient=X7R, Tolerance=±10%, Voltage - Rated=50V
C108 C109 C122 C124: library part capcc03139, "CAP CER 4.7UF 10V X5R 0402", Manufacturer="TDK Corporation", Operating Temperature="-55°C ~ 85°C", Ratings=-, Supplier Part Number 1=445-175214-1-ND, Temperature Coefficient=X5R, Tolerance=±10%, Voltage - Rated=10V
C113 C120 C139 C140 C144 C147 C157 C165: library part capcc09264, "CAP CER 1UF 10V X5R 0201", Manufacturer="Murata Electronics", Operating Temperature="-55°C ~ 85°C", Ratings=-, Supplier Part Number 1=490-GRM033R61A105ME44DCT-ND, Temperature Coefficient=X5R, Tolerance=±20%, Voltage - Rated=10V
C114 C118 C119 C145 C146 C164: library part capcc09251, "CAP CER 4.7UF 6.3V X5R 0201", Manufacturer="Murata Electronics", Operating Temperature="-55°C ~ 85°C", Ratings=-, Supplier Part Number 1=490-GRM033R60J475ME05DCT-ND, Temperature Coefficient=X5R, Tolerance=±20%, Voltage - Rated=6.3V
C128: library part capcc04216, "CAP CER 2200PF 50V X7R 0402", Manufacturer="KYOCERA AVX", Operating Temperature="-55°C ~ 125°C", Ratings=-, Supplier Part Number 1=478-5131-1-ND, Temperature Coefficient=X7R, Tolerance=±5%, Voltage - Rated=50V
C130 C131 C167 C170: library part capcc09395, "CAP CER 22UF 10V X7S 0805", Manufacturer="TDK Corporation", Operating Temperature="-55°C ~ 125°C", Ratings=-, Supplier Part Number 1=445-14560-1-ND, Temperature Coefficient=X7S, Tolerance=±20%, Voltage - Rated=10V
C171 C172 C173 C174: library part capcc03627, "CAP CER 47UF 16V X5R 1210", Manufacturer="KYOCERA AVX", Operating Temperature="-55°C ~ 85°C", Ratings=-, Supplier Part Number 1=478-11989-1-ND, Temperature Coefficient=X5R, Tolerance=±10%, Voltage - Rated=16V
C184 C187 C188 C189: library part capcc06830, "CAP CER 100UF 6.3V X5R 0805", Manufacturer="CAL-CHIP ELECTRONICS, INC.", Operating Temperature="-55°C ~ 85°C", Ratings=-, Supplier Part Number 1=2571-GMC21X5R107M6R3NTTR-ND, Temperature Coefficient=X5R, Tolerance=±20%, Voltage - Rated=6.3V
C204 C215 C233 C240 C247 C254: library part capcc09398, "CAP CER 10UF 6.3V X6S 0402", Manufacturer=Murata, Operating Temperature="-55°C ~ 105°C", Ratings=-, Supplier Part Number 1=490-13233-1-ND, Temperature Coefficient=X6S, Tolerance=±20%, Voltage - Rated=6.3V
C205: library part capcc02244, "CAP CER 0.47UF 16V X7S 0402", Manufacturer="TDK Corporation", Operating Temperature="-55°C ~ 125°C", Ratings=-, Supplier Part Number 1=445-174768-1-ND, Temperature Coefficient=X7S, Tolerance=±10%, Voltage - Rated=16V
C208 C209 C221 C222 C230 C237 C244 C251: library part capcc02750, "CAP CER 1UF 25V X5R 0402", Manufacturer="TDK Corporation", Operating Temperature="-55°C ~ 85°C", Ratings=-, Supplier Part Number 1=445-9066-1-ND, Temperature Coefficient=X5R, Tolerance=±10%, Voltage - Rated=25V
C213 C214 C216 C217 C223 C224 C225 C226: library part capcc09408, "CAP CER 100UF 6.3V X7S 1210", Manufacturer=Murata, Ratings=-, Supplier Part Number 1=490-GRT32EC70J107ME13LCT-ND, Temperature Coefficient=X7S, Tolerance=±20%, Voltage - Rated=6.3V
D1 D2 D3: library part cmp00247, "LED GREEN CLEAR CHIP SMD", Alt Manufacturer=-, Color=Green, Current Rating (Amps)=20mA, Manufacturer="Lite-On Inc.", Supplier Part Number 1=160-1888-1-ND, Voltage - Forward (Vf) (Typ)=3.2V
D4: library part cmp00440, "24.4V Clamp 24.6A Ipp Tvs Diode", Alt Manufacturer=-, Manufacturer=Littlefuse, Supplier Part Number 1=SMBJ15CALFCT-ND
D5: library part cmp00438, "DIODE SCHOTTKY 30V 1A SOD123", Alt Manufacturer="Rohm Semiconductor", Alt PartNumber=RB160M-30TR, Color=-, Manufacturer=Onsemi, Supplier Part Number 1=MBR130T1GOSCT-ND
D6: "Diode Array 1 Pair Common Cathode 20 V 400mA (DC)", Alt Manufacturer=-, Manufacturer="Diodes Inc", Supplier Part Number 1=SDM40E20LC-7DICT-ND
F1: library part cmp00082, "FUSE BOARD MOUNT 2.5A 32VDC 1206", Alt Manufacturer=-, Current Rating (Amps)="2.5 A", Manufacturer="Bourns Inc.", Supplier Part Number 1=SF-1206FP250-2CT-ND, Voltage Rating - DC="32 V"
F2: library part cmp00325, "EMI Filter Circuits 40 DB 50V 10A", Alt Manufacturer=-, Manufacturer="Murata Electronics", Supplier Part Number 1=81-BNX002-11
FB1 FB2 FB3 FB4 FB5 FB6 FB7 FB8 FB9 FB10 FB11: library part dcp00004, "8.5 Ohms @ 100 MHz 1 Power Line Ferrite Bead 0603 (1608 Metric) 8A 4mOhm", Current=8A, Manufacturer=Murata, Operating Temperature="-55°C ~ 125°C", Supplier Part Number 1=490-BLE18PS080SN1DCT-ND, Temperature Coefficient=-
FC1: library part dcp00001, "Feed through capactior 27uF", Current=6A, Manufacturer=Murata, Operating Temperature="-40°C ~ 85°C", Supplier Part Number 1=490-6984-1-ND, Temperature Coefficient=-, Tolerance=±20%, Voltage - Rated=6.3V
FID1 FID2 FID3: library part cmp00099, Alt Manufacturer=-
H2 H4: library part cmp00097, "Hex Standoff Threaded #4-40 Stainless Steel 1.250\" (31.75mm) 1 1/4", Alt Manufacturer=-, Manufacturer="RAF Electronic Hardware", Supplier Part Number 1=1772-1827-ND
J1 J2 J3 J4 J5 J6 J7 J8 J9 J10 J11 J12 J37: library part cmp00028, "SMA Connector Jack, Female Socket 50Ohm Surface Mount, Through Hole Solder", Alt Manufacturer=-, Manufacturer="Amphenol RF", Supplier Part Number 1=ACX1962-ND
J13 J41 J42: "Header, 50mil, 8x2, Gold, TH", Alt Manufacturer=-, Manufacturer="Sullins Connector Solutions", Supplier Part Number 1=S9015E-08-ND
J14 J16 J32 J33 J35 J36: library part cmp00032, "SMP Connector Plug, Male Pin 50Ohm Surface Mount Solder", Alt Manufacturer=-, Manufacturer=Molex, Supplier Part Number 1=WM3891CT-ND, Voltage_V=335V
J15 J17 J18: "Header, 100mil, 2x1, Gold, TH", Alt Manufacturer="Sullins Connector Solutions", Alt PartNumber=PBC02SAAN, Color=-, Manufacturer=Samtec, Supplier Part Number 1=S1011E-02-ND
J19 J24 J25 J26 J27 J30 J34 J38 J39 J40 J45: library part TSW-102-14-L-S, "Header, 100mil, 2x1, Gold, TH", Alt Manufacturer="Sullins Connector Solutions", Alt PartNumber=PBC02SAAN, Color=-, Manufacturer=Samtec, Supplier Part Number 1=S1011E-02-ND
J20 J23: "\"L\" Configuration Headers Connector Header Through Hole 3 position 100mils", Alt Manufacturer=-
J21 J22: "Header, 50mil, 5x1, Gold, TH", Alt Manufacturer=-, Manufacturer="Sullins Connector Solutions", Supplier Part Number 1=S9014E-05-ND
J28: library part cmp00061, "FTDI Dongle EVM Mating connector and standoff holes", Alt Manufacturer=-, Manufacturer=Samtec, Supplier Part Number 1=SAM8180-ND
J29: library part "VITA Male FMC", "FMC, High Density Array, Male", Alt Manufacturer=-, Manufacturer=Samtec, Supplier Part Number 1=SAM8730-ND
J31: library part cmp00022, "Power Jack, mini, 2.1mm OD, R/A, TH", Alt Manufacturer=-, Manufacturer=Switchcraft, Supplier Part Number 1=SC1313-ND
J43 J44: "8x2 Headers & Wire Housings Microfit 3.0 RA PTH clip DR Tin 16 Ckt", Alt Manufacturer=-, Manufacturer=Molex, Supplier Part Number 1=538-43045-1602
LBL1: library part cmp00106, "Thermal Transfer Printable Labels, 0.650\" W x 0.200\" H - 10,000 per roll", Alt Manufacturer=-, Manufacturer=Brady, Supplier Part Number 1=2267-THT-14-423-10-ND
LOGO1: library part cmp00317, Alt Manufacturer=-, PartNumber="ESD Logo"
Logo2: library part cmp00100, "IEC 61010-1 Hot Surface Warning", Alt Manufacturer=-, PartNumber=IEC_HotSurface
Logo3: library part cmp00104, "Texas Instrument Corporate Signature", Alt Manufacturer=-, PartNumber="TI Bug"
Logo4: library part cmp00103, "CE_Mark", Alt Manufacturer=-
Logo5: library part CMP-0074847-1, "FCC_disclaimer"
Logo6: library part cmp00101, Alt Manufacturer=-, PartNumber=WEEE_Minimum
Logo12: library part cmp00105, "FDL", Alt Manufacturer=-
MP1: library part cmp00111, "Heat Sink Passive BGA Straight Adhesive 9.3C/W Black Anodized", Alt Manufacturer=-, Manufacturer="Advanced Thermal Solutions", Supplier Part Number 1=ATS1230-ND
MP2: library part cmp00110, "Fan Tubeaxial 5VDC Square - 17mm L x 17mm H Sleeve 0.636 CFM (0.018m³/min) 2 Wire Leads", Alt Manufacturer=-, Manufacturer="Nidec Copal", PartNumber=F17HA-05HC, Supplier Part Number 1=563-1426-ND
NT1 NT2 NT3 NT4 NT5 NT6 NT7 NT8: library part CMP-0078142-6, "Single point connection between nets.", Manufacturer=N/A
PP1 PP2 PP3 PP4 PP5: "Probe Point that can be used in lue of a test point", Alt Manufacturer=-
Q1: library part cmp00159, "MOSFET, N-CH, 20 V, 10 A", Alt Manufacturer=-, Manufacturer="Texas Instruments", Supplier Part Number 1=296-39992-1-ND
R1 R2 R6 R7 R8 R9 R13 R14 R19 R20 R24 R25 R26 R27 R31 R32: library part RSMD020101700, "Thick Film Resistors - SMD 8.66Ohms 1/20W 0201 1%", Manufacturer=Yageo, Operating Temperature="-55°C ~ 125°C", Power (Watts)="0.05W, 1/20W", Resistance="8.66 Ω", Supplier Part Number 1=13-RC0201FR-078R66LCT-ND, Temperature Coefficient="- 100 PPM / C, + 350 PPM / C", Tolerance=±1%
R3 R5 R10 R12 R21 R23 R28 R30: library part RSMD020100157, "RES SMD 140 OHM 1% 1/20W 0201", Manufacturer="Panasonic Electronic Components", Operating Temperature="-55°C ~ 125°C", Power (Watts)="0.05W, 1/20W", Resistance="140 Ω", Supplier Part Number 1=P122727CT-ND, Temperature Coefficient=±200ppm/°C, Tolerance=±1%
R4 R11 R22 R29: library part RSMD020100143, "RES SMD 1K OHM 1% 1/20W 0201", Manufacturer="Panasonic Electronic Components", Operating Temperature="-55°C ~ 125°C", Power (Watts)="0.05W, 1/20W", Resistance="1 kΩ", Supplier Part Number 1=P122413CT-ND, Temperature Coefficient=±200ppm/°C, Tolerance=±1%
R15 R16 R33 R41 R42 R43 R44 R45 R49 R54 R55 R58 R61 R62 R63 R68 R69 R70 R80 R81 R82 R84 R164 R166 R167 R168 R169 R170 R171 R172 R173 R174 R177 R181 R182 R183 R184 R185 R186 R197 R198 R200 R201 R204 R205 R217 R218 R219: library part RSMD020101699, "RES SMD 0 OHM JUMPER 1/20W 0201", Manufacturer="Panasonic Electronic Components", Operating Temperature="-55°C ~ 125°C", Power (Watts)="0.05W, 1/20W", Resistance="0 Ω", Supplier Part Number 1=P15979CT-ND, Tolerance=Jumper
R17: library part CMP-0028070-1, "RES, 100, 1%, 0.05 W, 0201", Manufacturer="Yageo America", Power_W=50mW, Supplier Part Number 1=603-RC0201FS-7D100RL, TempCo="200 ppm/C", Tolerance_%=1%, Value2=0.05W, Value_Code=100R, ValueDisplayed=100
R18: library part RSMD020100063, "RES SMD 16 OHM 1% 1/20W 0201", Manufacturer="Panasonic Electronic Components", Operating Temperature="-55°C ~ 125°C", Power (Watts)="0.05W, 1/20W", Resistance="16 Ω", Supplier Part Number 1=P122773CT-ND, Temperature Coefficient=±200ppm/°C, Tolerance=±1%
R34 R35 R36 R37 R38 R39: library part RSMD020100132, "RES SMD 560 OHM 1% 1/20W 0201", Manufacturer="Panasonic Electronic Components", Operating Temperature="-55°C ~ 125°C", Power (Watts)="0.05W, 1/20W", Resistance="560 Ω", Supplier Part Number 1=P123075CT-ND, Temperature Coefficient=±200ppm/°C, Tolerance=±1%
R40 R46 R47 R48 R50 R57 R65 R71 R72 R73 R74 R75 R79 R88 R162 R163 R165 R189 R190 R191 R192 R193 R194 R195 R196 R210 R211 R212 R213 R214 R215 R216 R237 R238: library part RSMD020100762, "RES SMD 10K OHM 1% 1/20W 0201", Manufacturer="Panasonic Electronic Components", Operating Temperature="-55°C ~ 125°C", Power (Watts)="0.05W, 1/20W", Resistance="10 kΩ", Supplier Part Number 1=P122414CT-ND, Temperature Coefficient=±200ppm/°C, Tolerance=±1%
R51: library part RSMD080507476, "RES 100 OHM 1% 1/2W 0805", Manufacturer="Panasonic Electronic Components", Operating Temperature="-55°C ~ 175°C", Power (Watts)=1/2W, Ratings=AEC-Q200, Resistance="100 Ω", Supplier Part Number 1=10-ERJ-HP6F1000VCT-ND, Temperature Coefficient=±100ppm/°C, Tolerance=±1%
R52 R56: library part RSMD020100508, "RES SMD 4.7K OHM 1% 1/20W 0201", Manufacturer="Panasonic Electronic Components", Operating Temperature="-55°C ~ 125°C", Power (Watts)="0.05W, 1/20W", Resistance="4.7 kΩ", Supplier Part Number 1=P123031CT-ND, Temperature Coefficient=±200ppm/°C, Tolerance=±1%
R53 R59 R78 R155 R156 R161 R175 R176 R178 R180 R187 R188 R207: library part RSMD020100289, "RES SMD 100 OHM 1% 1/20W 0201", Manufacturer="Panasonic Electronic Components", Operating Temperature="-55°C ~ 125°C", Power (Watts)="0.05W, 1/20W", Resistance="100 Ω", Supplier Part Number 1=P122654CT-ND, Temperature Coefficient=±200ppm/°C, Tolerance=±1%
R60 R64 R206 R227 R228 R229 R230 R231 R232 R233 R234 R235 R236: library part RSMD040200001, "RES SMD 0 OHM JUMPER 1/10W 0402", Manufacturer="Panasonic Electronic Components", Operating Temperature="-55°C ~ 155°C", Power (Watts)="0.1W, 1/10W", Ratings=AEC-Q200, Resistance="0 Ω", Supplier Part Number 1=P0.0JCT-ND, Temperature Coefficient=-, Tolerance=Jumper
R66 R67: library part RSMD020100617, "RES SMD 3.74K OHM 1% 1/20W 0201", Manufacturer="Panasonic Electronic Components", Operating Temperature="-55°C ~ 125°C", Power (Watts)="0.05W, 1/20W", Resistance="3.74 kΩ", Supplier Part Number 1=P122972CT-ND, Temperature Coefficient=±200ppm/°C, Tolerance=±1%
R76 R77 R157 R158 R159 R160 R208 R209: library part RSMD020100177, "RES SMD 49.9 OHM 1% 1/20W 0201", Manufacturer="Panasonic Electronic Components", Operating Temperature="-55°C ~ 125°C", Power (Watts)="0.05W, 1/20W", Resistance="49.9 Ω", Supplier Part Number 1=P123049CT-ND, Temperature Coefficient=±200ppm/°C, Tolerance=±1%
R83: library part RSMD040202043, "RES 3.9K OHM 5% 1/10W 0402", Manufacturer="Panasonic Electronic Components", Operating Temperature="-55°C ~ 175°C", Power (Watts)="0.1W, 1/10W", Ratings=AEC-Q200, Resistance="3.9 kΩ", Supplier Part Number 1=10-ERJ-H2GJ392XCT-ND, Temperature Coefficient=±200ppm/°C, Tolerance=±5%
R85 R86 R199: library part RSMD020100147, "RES SMD 220 OHM 1% 1/20W 0201", Manufacturer="Panasonic Electronic Components", Operating Temperature="-55°C ~ 125°C", Power (Watts)="0.05W, 1/20W", Resistance="220 Ω", Supplier Part Number 1=P122831CT-ND, Temperature Coefficient=±200ppm/°C, Tolerance=±1%
R87: library part RSMD040200007, "RES SMD 1K OHM 1% 1/5W 0402", Manufacturer="Panasonic Electronic Components", Operating Temperature="-55°C ~ 155°C", Power (Watts)="0.2W, 1/5W", Ratings=AEC-Q200, Resistance="1 kΩ", Supplier Part Number 1=P17224CT-ND, Temperature Coefficient=±100ppm/°C, Tolerance=±1%
R89 R90 R91 R92 R93 R94 R95 R96 R97 R98 R99 R100 R101: library part RSMD020100606, "RES SMD 2.2K OHM 1% 1/20W 0201", Manufacturer="Panasonic Electronic Components", Operating Temperature="-55°C ~ 125°C", Power (Watts)="0.05W, 1/20W", Resistance="2.2 kΩ", Supplier Part Number 1=P122832CT-ND, Temperature Coefficient=±200ppm/°C, Tolerance=±1%
R102 R112 R118 R123 R125 R127 R129 R131 R137 R143 R149 R179: library part RSMD040200311, "RES SMD 10K OHM 1% 1/5W 0402", Manufacturer="Panasonic Electronic Components", Operating Temperature="-55°C ~ 155°C", Power (Watts)="0.2W, 1/5W", Ratings=AEC-Q200, Resistance="10 kΩ", Supplier Part Number 1=P17230CT-ND, Temperature Coefficient=±100ppm/°C, Tolerance=±1%
R103: library part OtherRs00002, "RES SHUNT, 0603, 0.002 OHM, 1%,", Manufacturer="Stackpole Electronics Inc", Operating Temperature="-55°C ~ 155°C", Power (Watts)="0.333W, 1/3W", Ratings=AEC-Q200, Resistance="2 mΩ", Supplier Part Number 1=738-CSS0603FT2L00CT-ND, Temperature Coefficient=±150ppm/°C, Tolerance=±1%
R104 R105 R106 R107: library part OtherRs00003, "RES 0.01 OHM 1% 1/3W 0603", Manufacturer="Stackpole Electronics Inc", Operating Temperature="-55°C ~ 150°C", Power (Watts)="0.333W, 1/3W", Ratings=AEC-Q200, Resistance="10 mΩ", Supplier Part Number 1=738-CSS0603FT10L0CT-ND, Temperature Coefficient=±50ppm/°C, Tolerance=±1%
R108 R224: library part RSMD040200354, "RES SMD 100K OHM 5% 1/10W 0402", Manufacturer="Panasonic Electronic Components", Operating Temperature="-55°C ~ 155°C", Power (Watts)="0.1W, 1/10W", Ratings=AEC-Q200, Resistance="100 kΩ", Supplier Part Number 1=P100KJCT-ND, Temperature Coefficient=±200ppm/°C, Tolerance=±5%
R109: library part RSMD040203665, "RES SMD 76.8K OHM 1% 1/10W 0402", Manufacturer="Panasonic Electronic Components", Operating Temperature="-55°C ~ 155°C", Power (Watts)="0.1W, 1/10W", Ratings=AEC-Q200, Resistance="76.8 kΩ", Supplier Part Number 1=P76.8KLCT-ND, Temperature Coefficient=±100ppm/°C, Tolerance=±1%
R110 R124: library part RSMD040200983, "RES SMD 17.4K OHM 1% 1/10W 0402", Manufacturer="Panasonic Electronic Components", Operating Temperature="-55°C ~ 155°C", Power (Watts)="0.1W, 1/10W", Ratings=AEC-Q200, Resistance="17.4 kΩ", Supplier Part Number 1=P17.4KLCT-ND, Temperature Coefficient=±100ppm/°C, Tolerance=±1%
R111 R226: library part RSMD040200897, "RES SMD 16.2K OHM 1% 1/10W 0402", Manufacturer="Panasonic Electronic Components", Operating Temperature="-55°C ~ 155°C", Power (Watts)="0.1W, 1/10W", Ratings=AEC-Q200, Resistance="16.2 kΩ", Supplier Part Number 1=P16.2KLCT-ND, Temperature Coefficient=±100ppm/°C, Tolerance=±1%
R113 R115 R225: library part RSMD040202587, "RES SMD 4.7K OHM 1% 1/5W 0402", Manufacturer="Panasonic Electronic Components", Operating Temperature="-55°C ~ 155°C", Power (Watts)="0.2W, 1/5W", Ratings=AEC-Q200, Resistance="4.7 kΩ", Supplier Part Number 1=P17228CT-ND, Temperature Coefficient=±100ppm/°C, Tolerance=±1%
R114: library part RSMD040200802, "RES SMD 15.4KOHM 0.1% 1/16W 0402", Manufacturer="Panasonic Electronic Components", Operating Temperature="-55°C ~ 155°C", Power (Watts)="0.063W, 1/16W", Ratings=AEC-Q200, Resistance="15.4 kΩ", Supplier Part Number 1=P17733CT-ND, Temperature Coefficient=±15ppm/°C, Tolerance=±0.1%
R116: library part RSMD040203748, "RES SMD 80.6K OHM 1% 1/10W 0402", Manufacturer="Panasonic Electronic Components", Operating Temperature="-55°C ~ 155°C", Power (Watts)="0.1W, 1/10W", Ratings=AEC-Q200, Resistance="80.6 kΩ", Supplier Part Number 1=P80.6KLCT-ND, Temperature Coefficient=±100ppm/°C, Tolerance=±1%
R117: library part RSMD040202614, "RES SMD 4.87KOHM 0.1% 1/16W 0402", Manufacturer="Panasonic Electronic Components", Operating Temperature="-55°C ~ 155°C", Power (Watts)="0.063W, 1/16W", Ratings=AEC-Q200, Resistance="4.87 kΩ", Supplier Part Number 1=P17862CT-ND, Temperature Coefficient=±15ppm/°C, Tolerance=±0.1%
R119: library part RSMD040202950, "RES SMD 5.23KOHM 0.1% 1/16W 0402", Manufacturer="Panasonic Electronic Components", Operating Temperature="-55°C ~ 155°C", Power (Watts)="0.063W, 1/16W", Ratings=AEC-Q200, Resistance="5.23 kΩ", Supplier Part Number 1=P5.23KDCCT-ND, Temperature Coefficient=±25ppm/°C, Tolerance=±0.1%
R120 R121: library part RSMD040200413, "RES SMD 11K OHM 0.1% 1/16W 0402", Manufacturer="Panasonic Electronic Components", Operating Temperature="-55°C ~ 155°C", Power (Watts)="0.063W, 1/16W", Ratings=AEC-Q200, Resistance="11 kΩ", Supplier Part Number 1=P11KDCCT-ND, Temperature Coefficient=±25ppm/°C, Tolerance=±0.1%
R122 R128: library part RSMD040200348, "RES SMD 10.7KOHM 0.1% 1/16W 0402", Manufacturer="Panasonic Electronic Components", Operating Temperature="-55°C ~ 155°C", Power (Watts)="0.063W, 1/16W", Ratings=AEC-Q200, Resistance="10.7 kΩ", Supplier Part Number 1=P17709CT-ND, Temperature Coefficient=±15ppm/°C, Tolerance=±0.1%
R126: library part RSMD040202348, "RES SMD 36K OHM 0.1% 1/16W 0402", Manufacturer="Panasonic Electronic Components", Operating Temperature="-55°C ~ 155°C", Power (Watts)="0.063W, 1/16W", Ratings=AEC-Q200, Resistance="36 kΩ", Supplier Part Number 1=P36KCNCT-ND, Temperature Coefficient=±15ppm/°C, Tolerance=±0.1%
R130: library part RSMD040203089, "RES SMD 53.6K OHM 1% 1/10W 0402", Manufacturer="Panasonic Electronic Components", Operating Temperature="-55°C ~ 155°C", Power (Watts)="0.1W, 1/10W", Ratings=AEC-Q200, Resistance="53.6 kΩ", Supplier Part Number 1=P53.6KLCT-ND, Temperature Coefficient=±100ppm/°C, Tolerance=±1%
R132 R138: library part RSMD040203743, "RES SMD 8.87KOHM 0.1% 1/16W 0402", Manufacturer="Panasonic Electronic Components", Operating Temperature="-55°C ~ 155°C", Power (Watts)="0.063W, 1/16W", Ratings=AEC-Q200, Resistance="8.87 kΩ", Supplier Part Number 1=P8.87KDCCT-ND, Temperature Coefficient=±25ppm/°C, Tolerance=±0.1%
R133 R139: library part RSMD040203107, "RES SMD 54.9K OHM 1% 1/10W 0402", Manufacturer="Panasonic Electronic Components", Operating Temperature="-55°C ~ 155°C", Power (Watts)="0.1W, 1/10W", Ratings=AEC-Q200, Resistance="54.9 kΩ", Supplier Part Number 1=P54.9KLCT-ND, Temperature Coefficient=±100ppm/°C, Tolerance=±1%
R134 R140: library part RSMD040201567, "RES SMD 23.2KOHM 0.1% 1/16W 0402", Manufacturer="Panasonic Electronic Components", Operating Temperature="-55°C ~ 155°C", Power (Watts)="0.063W, 1/16W", Ratings=AEC-Q200, Resistance="23.2 kΩ", Supplier Part Number 1=P17986CT-ND, Temperature Coefficient=±10ppm/°C, Tolerance=±0.1%
R135 R141 R147 R153: library part RSMD040200547, "RES SMD 12.4K OHM 1% 1/10W 0402", Manufacturer="Panasonic Electronic Components", Operating Temperature="-55°C ~ 155°C", Power (Watts)="0.1W, 1/10W", Ratings=AEC-Q200, Resistance="12.4 kΩ", Supplier Part Number 1=P12.4KLCT-ND, Temperature Coefficient=±100ppm/°C, Tolerance=±1%
R136 R142 R148 R154: library part RSMD040200357, "RES SMD 100K OHM 0.1% 1/16W 0402", Manufacturer="Panasonic Electronic Components", Operating Temperature="-55°C ~ 155°C", Power (Watts)="0.063W, 1/16W", Ratings=AEC-Q200, Resistance="100 kΩ", Supplier Part Number 1=P100KDCCT-ND, Temperature Coefficient=±25ppm/°C, Tolerance=±0.1%
R144 R150: library part RSMD040200901, "RES SMD 16.5KOHM 0.1% 1/16W 0402", Manufacturer="Panasonic Electronic Components", Operating Temperature="-55°C ~ 155°C", Power (Watts)="0.063W, 1/16W", Ratings=AEC-Q200, Resistance="16.5 kΩ", Supplier Part Number 1=P17954CT-ND, Temperature Coefficient=±10ppm/°C, Tolerance=±0.1%
R145 R151: library part RSMD040203878, "RES SMD 88.7KOHM 0.1% 1/16W 0402", Manufacturer="Panasonic Electronic Components", Operating Temperature="-55°C ~ 155°C", Power (Watts)="0.063W, 1/16W", Ratings=AEC-Q200, Resistance="88.7 kΩ", Supplier Part Number 1=P88.7KDCCT-ND, Temperature Coefficient=±25ppm/°C, Tolerance=±0.1%
R146 R152: library part RSMD040202420, "RES SMD 37.4KOHM 0.1% 1/16W 0402", Manufacturer="Panasonic Electronic Components", Operating Temperature="-55°C ~ 155°C", Power (Watts)="0.063W, 1/16W", Ratings=AEC-Q200, Resistance="37.4 kΩ", Supplier Part Number 1=P18046CT-ND, Temperature Coefficient=±10ppm/°C, Tolerance=±0.1%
